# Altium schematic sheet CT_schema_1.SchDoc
size 512 x 499 mm
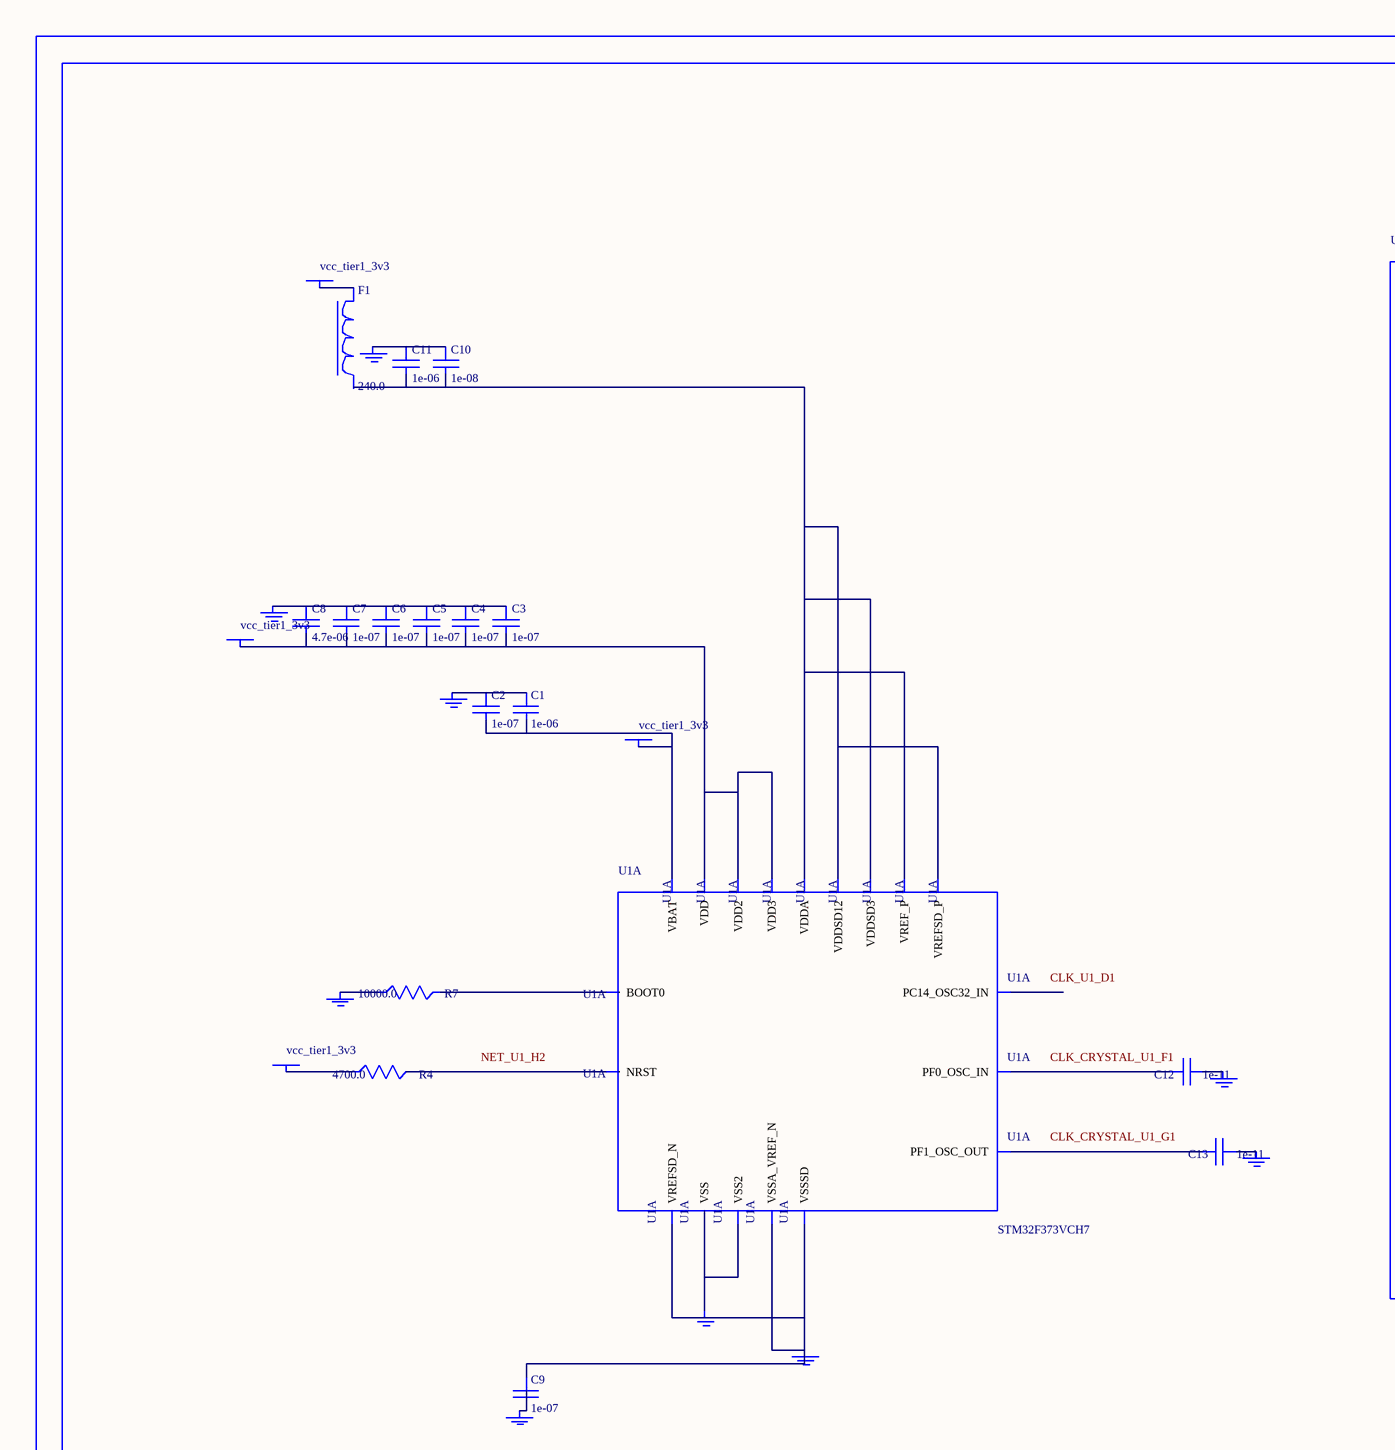
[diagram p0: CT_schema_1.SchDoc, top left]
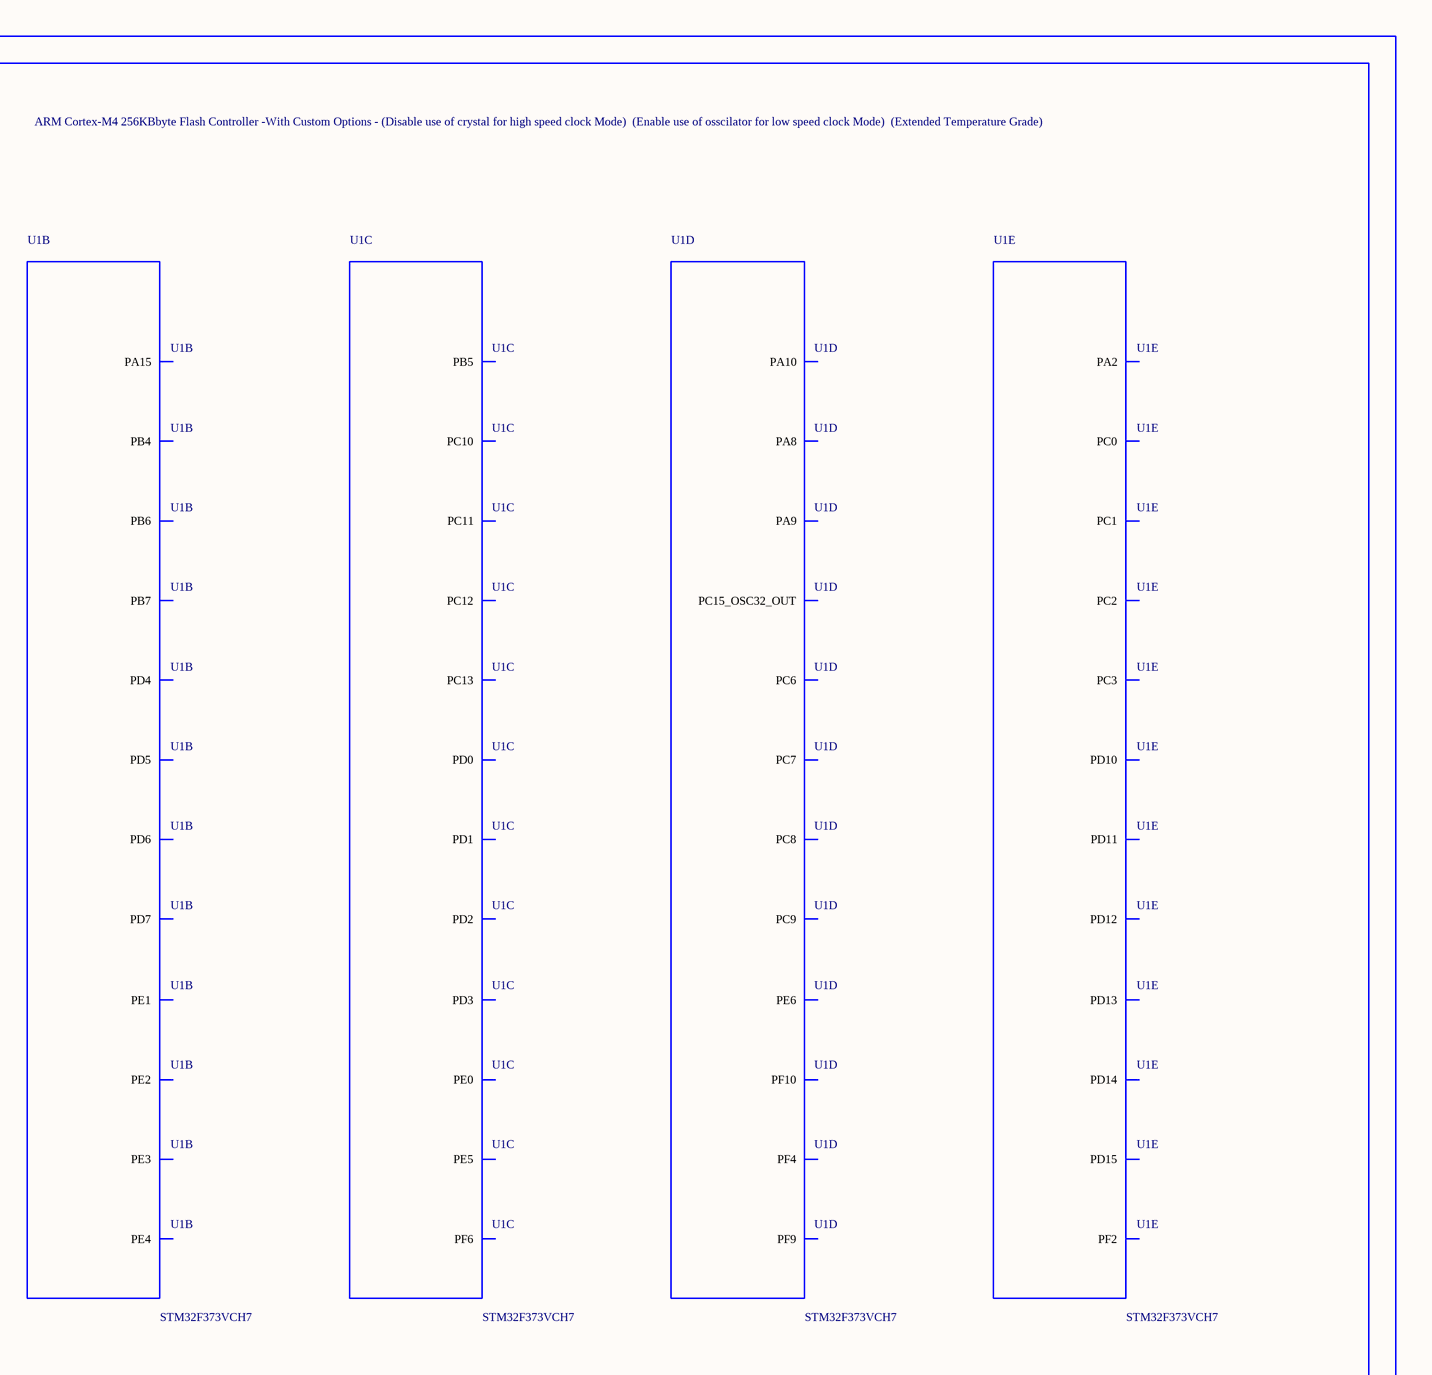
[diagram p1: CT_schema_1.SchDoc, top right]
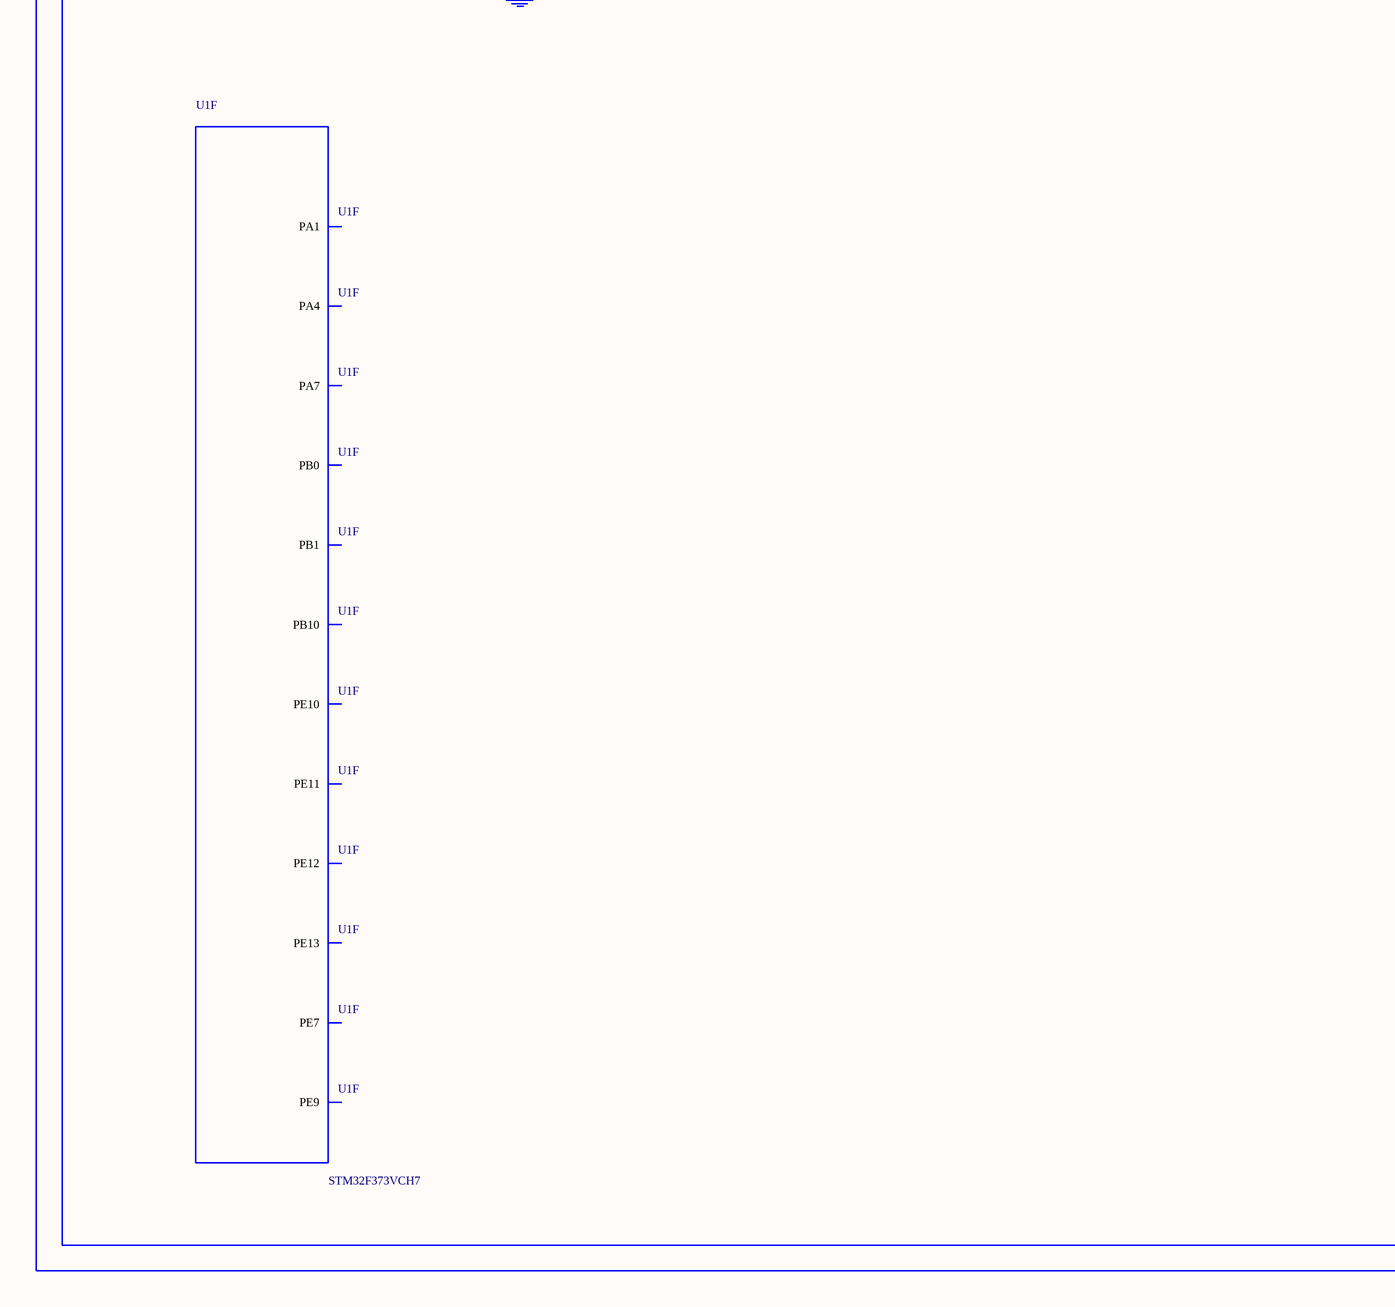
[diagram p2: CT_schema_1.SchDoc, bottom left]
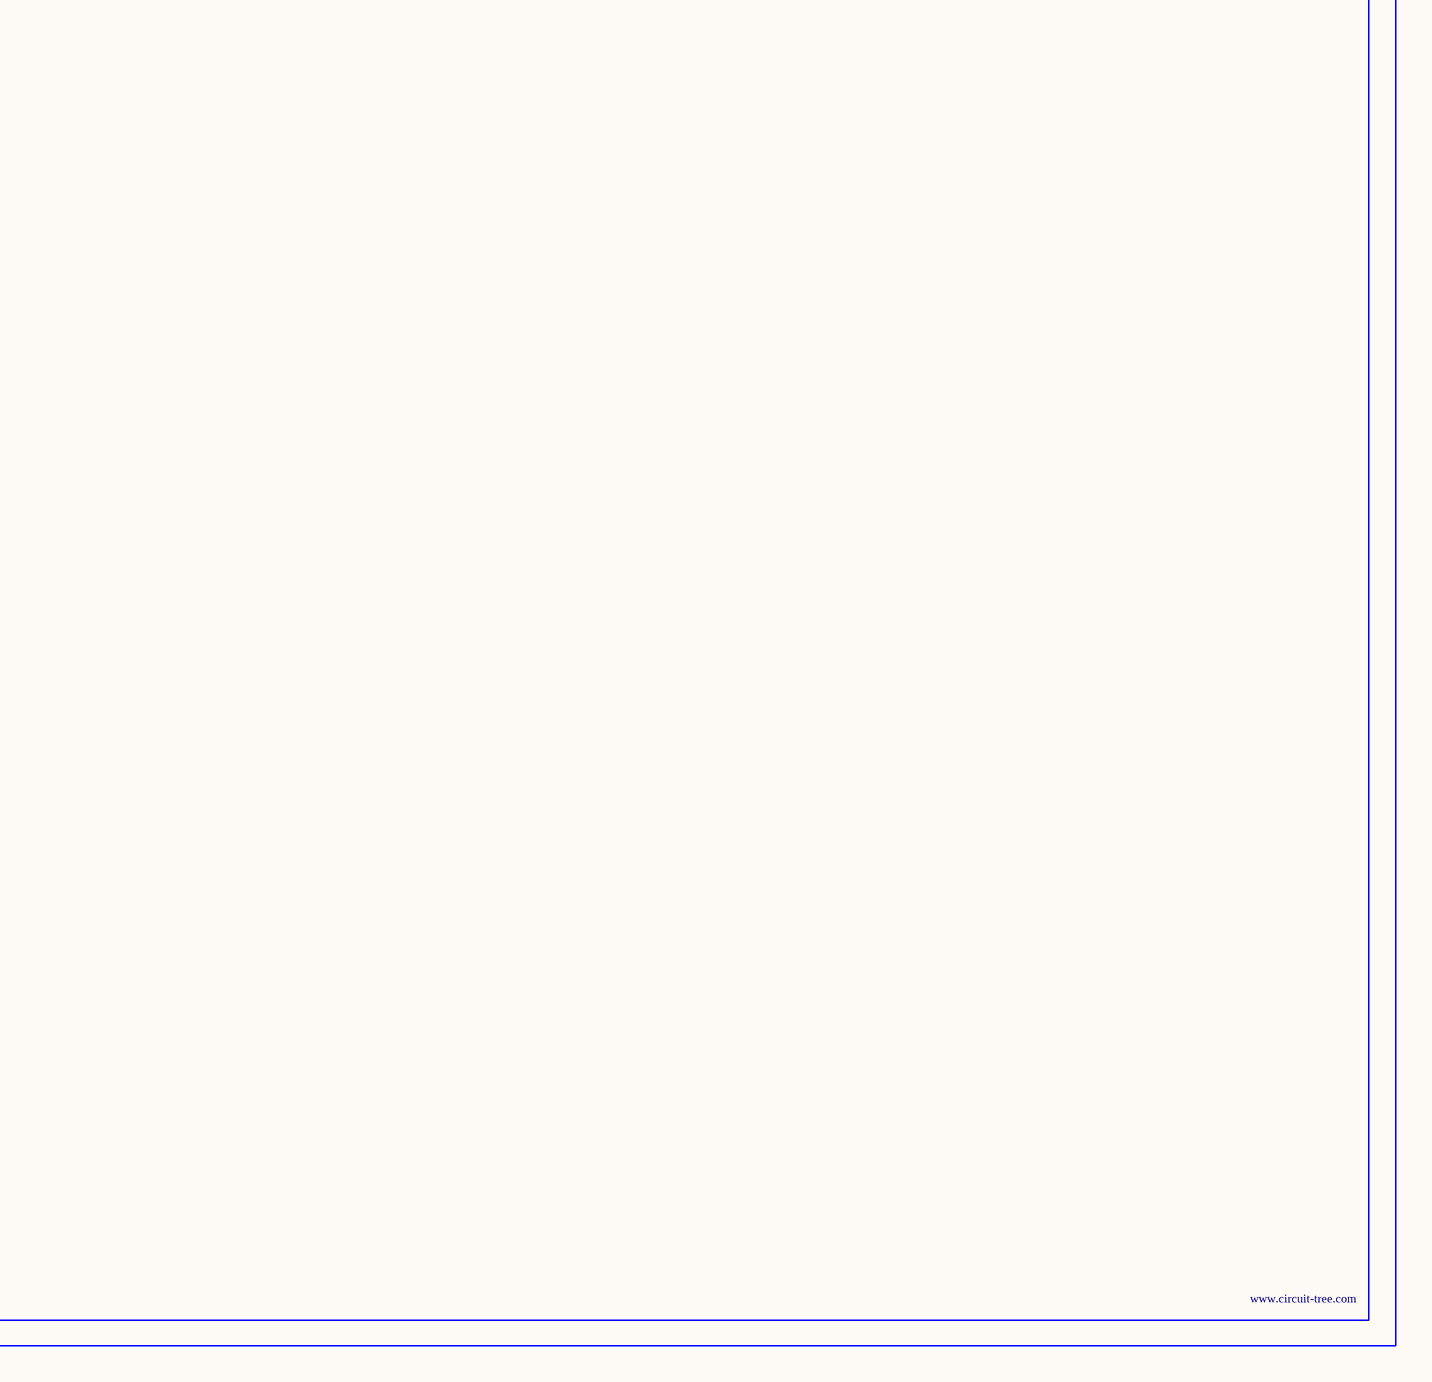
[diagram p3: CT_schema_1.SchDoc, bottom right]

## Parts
BORDER0  (no value)
C1  1e-06  [C0603]
C2  1e-07  [C0603]
C3  1e-07  [C0603]
C4  1e-07  [C0603]
C5  1e-07  [C0603]
C6  1e-07  [C0603]
C7  1e-07  [C0603]
C8  4.7e-06  [C0603]
C9  1e-07  [C0603]
C10  1e-08  [C0603]
C11  1e-06  [C0603]
C12  1e-11  [C0402]
C13  1e-11  [C0402]
F1  240.0  [L0603]
GND_INSTANCE_0_0  (no value)
GND_INSTANCE_0_1  (no value)
GND_INSTANCE_0_2  (no value)
GND_INSTANCE_0_3  (no value)
GND_INSTANCE_0_4  (no value)
GND_INSTANCE_0_5  (no value)
GND_INSTANCE_0_6  (no value)
GND_INSTANCE_0_7  (no value)
GND_INSTANCE_0_8  (no value)
POWER_INSTANCE_0_0  vcc_tier1_3v3
POWER_INSTANCE_0_1  vcc_tier1_3v3
POWER_INSTANCE_0_2  vcc_tier1_3v3
POWER_INSTANCE_0_3  vcc_tier1_3v3
R4  4700.0  [R0603]
R7  10000.0  [R0603]
U1  STM32F373VCH7  [UFBGA100]  (parts A,B,C,D,E,F of 10)

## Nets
NetC1_1: C1.1 C2.1 GND_INSTANCE_0_0.0(GND)
NetC1_2: C1.2 C2.2 POWER_INSTANCE_0_0.0(PWR) U1.E2(VBAT)
NetC3_1: C3.1 C4.1 C5.1 C6.1 C7.1 C8.1 GND_INSTANCE_0_2.0(GND)
NetC3_2: C3.2 C4.2 C5.2 C6.2 C7.2 C8.2 POWER_INSTANCE_0_2.0(PWR) U1.C4(VDD) U1.G11(VDD2) U1.H3(VDD3)
NetC9_1: C9.1 GND_INSTANCE_0_7.0(GND) U1.F12(VSSSD) U1.K1(VSSA_VREF_N) U1.L11(VREFSD_N)
NetC9_2: C9.2 GND_INSTANCE_0_4.0(GND)
NetC10_1: C10.1 C11.1 GND_INSTANCE_0_1.0(GND)
NetC10_2: C10.2 C11.2 U1.G12(VDDSD12) U1.K12(VREFSD_P) U1.L1(VREF_P) U1.L12(VDDSD3) U1.M1(VDDA)
NetC12_1: C12.1 GND_INSTANCE_0_5.0(GND)
NetC12_2: C12.2 U1.F1(PF0_OSC_IN)
NetC13_1: C13.1 GND_INSTANCE_0_6.0(GND)
NetC13_2: C13.2 U1.G1(PF1_OSC_OUT)
NetF1_1: F1.1 POWER_INSTANCE_0_1.0(PWR)
NetGND_INSTANCE_0_3_0: GND_INSTANCE_0_3.0(GND) R7.1
NetGND_INSTANCE_0_8_0: GND_INSTANCE_0_8.0(GND) U1.D3(VSS) U1.F11(VSS2)
NetPOWER_INSTANCE_0_3_0: POWER_INSTANCE_0_3.0(PWR) R4.1
NetR4_2: R4.2 U1.H2(NRST)
NetR7_2: R7.2 U1.A4(BOOT0)

Not connected (* = marked no-connect by the designer): F1 2; U1 A1(PE3) A2(PE1) A5(PD7) A6(PD5) A7(PB4) A9(PA15) B1(PE4) B2(PE2) B4(PB7) B5(PB6) B6(PD6) B7(PD4) B8(PD3) B9(PD1) B10(PC12) B11(PC10) C1(PC13) C2(PE5) C3(PE0) C5(PB5) C8(PD2) C9(PD0) C10(PC11) C11(PF6) C12(PA10) D1(PC14_OSC32_IN) D2(PE6) D10(PA9) D11(PA8) D12(PC9) E1(PC15_OSC32_OUT) E3(PF4) E10(PC8) E11(PC7) E12(PC6) F2(PF9) G2(PF10) H1(PC0) H10(PD15) H11(PD14) H12(PD13) J1(PF2) J2(PC1) J3(PC2) J10(PD12) J11(PD11) J12(PD10) K2(PC3) K3(PA2) L8(PE10) L9(PE12) L10(PB10) M2(PA1) M3(PA4) M4(PA7) M5(PB0) M6(PB1) M7(PE7) M8(PE9) M9(PE11) M10(PE13)

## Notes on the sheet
- Labels drawn without touching a wire or pin: CLK_CRYSTAL_U1_F1, CLK_CRYSTAL_U1_G1, CLK_U1_D1, NET_U1_H2

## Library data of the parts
BORDER0 = BORDER_PAGE0
C1 C11 = C0603C105K3RACTU
C2-C7 C9 = 06035C104K4Z2A
C8 = GRM188R6YA475KE15D
C10 = 06035C103K4Z2A
C12 C13 = C0402C100K3GACTU
F1 = Z0603C241ASMST
GND_INSTANCE_0_0-GND_INSTANCE_0_8 = GND
POWER_INSTANCE_0_0-POWER_INSTANCE_0_3 = PWR
R4 = RC0603JR-074K7L
R7 = RC0603JR-0710KL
